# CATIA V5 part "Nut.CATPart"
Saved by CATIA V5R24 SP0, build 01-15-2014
Part number: Nut
Bounding box of the stored display mesh (mm): x -5.774 to 5.774, y -5 to 5, z 0 to 5
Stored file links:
  C:\Users\minsi\Google 드라이브\CDL_2019\00_CLASS\00_CAD\기말고사\DMU\Nut.CATPart
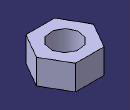
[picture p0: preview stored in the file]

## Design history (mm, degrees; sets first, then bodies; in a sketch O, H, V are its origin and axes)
Body1 (main body)
  Sketch1 on xy-plane, origin (0, 0, 0), H (1, 0, 0), V (0, 1, 0)
    point P1 (2.8868, 5)
    point P2 (-2.8868, 5)
    point P3 (-5.7735, 0)
    point P4 (-2.8868, -5)
    point P5 (2.8868, -5)
    point P6 (5.7735, 0)
    point P7 (0, 5)
    line L1 (2.8868, 5) -> (-2.8868, 5)
    line L2 (-2.8868, 5) -> (-5.7735, 0)
    line L3 (-5.7735, 0) -> (-2.8868, -5)
    line L4 (-2.8868, -5) -> (2.8868, -5)
    line L5 (2.8868, -5) -> (5.7735, 0)
    line L6 (5.7735, 0) -> (2.8868, 5)
    construction line L7 (0, 0) -> (0, 5)
    construction circle A1 centre (0, 0) radius 5.7735
    construction arc A2 centre (2.8868, -5) radius 5.7735 from (-2.8868, -5) to (5.7735, 0) cw
    construction arc A3 centre (-2.8868, 5) radius 5.7735 from (-5.7735, 0) to (2.8868, 5) ccw
    distance L1 L4 = 10
    angle L7 H = 90
    coincidence: A1 P1, A1 P2, A1 P3, A1 P4, A1 P5, A1 P6, A2 O, A3 O
    midpoint: P7 L1
    parallelism: L1 L4, L2 L5
  Pad1: profile Sketch1, direction (0, 0, 1), length 5
  Sketch2 on end face of Pad1, origin (1.0089, 0, 5), H (1, 0, 0), V (0, 1, 0)
    point P1 (-1.0089, 0)
    reference intersected line E1 through (-1.0089, 0) direction (0, 1) from yz-plane
    reference intersected line E2 through (0, 0) direction (-1, 0) from zx-plane
    coincidence: P1 E1, P1 E2
  Hole1: placed by Sketch2, at (0, 0, 5) direction (0, 0, -1), diameter 6, depth 10, V-bottom angle 120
